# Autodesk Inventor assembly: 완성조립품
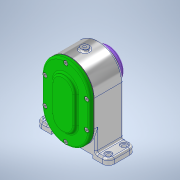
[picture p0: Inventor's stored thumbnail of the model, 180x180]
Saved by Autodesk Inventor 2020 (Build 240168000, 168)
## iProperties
Created: 2021-05
Part Number: 완성조립품
Document SubType Name: Assembly
Designer: Owner
Author: Owner
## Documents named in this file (19)
- C:\Users\Owner\Desktop\710507V1009\완성조립품.iam
- C:\Users\Owner\Desktop\710507V1009\본체.ipt
- C:\Users\Owner\Desktop\710507V1009\베어링 6001.ipt
- 베어링 6001.ipt
- C:\Users\Owner\Desktop\710507V1009\칼라.ipt
- C:\Users\Owner\Desktop\710507V1009\스퍼기어 A.ipt
- C:\Users\Owner\Desktop\710507V1009\스퍼기어 B.ipt
- C:\Users\Owner\Desktop\710507V1009\축 A.ipt
- C:\Users\Owner\Desktop\710507V1009\베어링 6002.ipt
- 베어링 6002.ipt
- C:\Users\Owner\Desktop\710507V1009\축 B.ipt
- C:\Users\Owner\Desktop\710507V1009\키 5 x 5 x 12.ipt
- C:\Users\Owner\Desktop\710507V1009\키 4 x 4 x 12.ipt
- C:\Users\Owner\Desktop\710507V1009\커버 A.ipt
- C:\Users\Owner\Desktop\710507V1009\볼트 M4.ipt
- C:\Users\Owner\Desktop\710507V1009\오일 실 12 22 7.ipt
- C:\Users\Owner\Desktop\710507V1009\개스킷 A.ipt
- C:\Users\Owner\Desktop\710507V1009\개스킷 B.ipt
- C:\Users\Owner\Desktop\710507V1009\커버 B.ipt
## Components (2 placed, 2 different names)
1. 개스킷 A:1
2. 개스킷 B:1
